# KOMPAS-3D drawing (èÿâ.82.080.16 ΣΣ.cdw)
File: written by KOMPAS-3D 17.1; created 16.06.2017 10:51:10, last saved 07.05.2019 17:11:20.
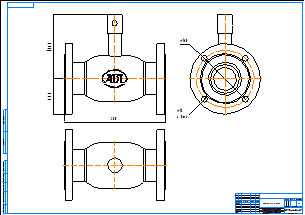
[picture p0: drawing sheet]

Sheet 1: A1, landscape

Title block, sheet 1: name: КШГ.82.080.16 фф; material: Внимание! Данный продукт является объектом авторского права ООО «Торговый Дом АДЛ». / Запрещается изменение, копирование, распространение / (в том числе путем копирования на другие сайты и ресурсы в Интернете) / или любое иное использование информации и объектов без предварительного / согласия правообладателя (ООО «Торговый Дом АДЛ»).; scale: 1:1; sheets: 1; organisation: ООО "Торговый дом АДЛ"; sheet format: A1; stored path: C:\Users\tra\Desktop\2д чертежи\Шаровые краны БИВАЛ\КШ_Бивал_серия_82_85\KOMPAS 2D\КШГ.82.080.16 фф.cdw

Views: Спереди 1, Проекционный вид 2, Проекционный вид 3
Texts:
  Klimkovich
  ADL
Dimensions and other numbers on the sheet: 280; 176,8; 97,5; 160; 18; 4 Отв.; 1:1; 1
